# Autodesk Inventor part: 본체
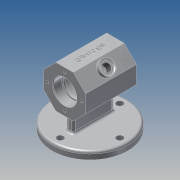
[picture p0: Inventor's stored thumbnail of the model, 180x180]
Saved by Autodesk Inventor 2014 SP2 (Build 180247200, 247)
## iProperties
Created: 2021-02
Part Number: 본체
Material: 알루미늄 6061
Document SubType Name: Modeling
Designer: kb542-10
Density: 2.71 g/cm^3
Appearance: 알루미늄 - 평지
Mass: 558.864 g
Surface Area: 511.644 cm^2
Volume: 206.223 cm^3
Author: kb542-10
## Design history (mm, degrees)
sketch "스케치1"
  geometry: L1 (11.995, -29.007)-(-12.03, -28.993); L2 (-12.03, -28.993)-(-29.007, -11.995); L3 (-29.007, -11.995)-(-28.993, 12.03); L4 (-28.993, 12.03)-(-11.995, 29.007); L5 (-11.995, 29.007)-(12.03, 28.993); L6 (12.03, 28.993)-(29.007, 11.995); L7 (29.007, 11.995)-(28.993, -12.03); L8 (28.993, -12.03)-(11.995, -29.007); 2 further points
  constraints: 16 end point, 1 coincident, 17 other
  dimensions: "d0" = 58 distance between parallel lines of L8 L4
extrude "돌출1" new body sketch "스케치1" stored distance "d1" = 70; taper "d2" = 0 deg
sketch "스케치2"
  geometry: L1 (12.03, 35)-(-11.995, 35) reference; L2 (-11.995, -35)-(12.03, -35) reference; L3 (29.007, 35)-(29.007, -35) reference; L4 (-28.993, 35)-(-28.993, -35) reference; L5 (0.018, 35)-(0.018, -35); L6 (16.018, 35)-(16.018, 23); L7 (16.018, 23)-(14.018, 23); L8 (14.018, 23)-(14.018, 20); L9 (14.018, 20)-(22.018, 20); L10 (22.018, 20)-(22.018, -20); L11 (22.018, -20)-(14.018, -20); L12 (14.018, -20)-(14.018, -23); L13 (14.018, -23)-(16.018, -23); L14 (16.018, -23)-(16.018, -35); L15 (16.018, 35)-(0.018, 35); L16 (16.018, -35)-(0.018, -35); 1 further point
  constraints: 24 end point, 7 parallel, 3 collinear, 3 perpendicular, 2 midpoint, 2 point on line
  dimensions: "d3" = 44 diameter of L10 L5; "d4" = 32 diameter of L6 L5; "d5" = 28 diameter of L8 L5; "d6" = 12 distance of L6.start L6.end; "d7" = 12 distance of L13.end L14.end; "d8" = 3 distance of L7.end L8.end; "d9" = 3 distance of L11.end L12.end
revolve "회전1" sketch "스케치2" stored, may be unused: angle "d10" = 90 deg
node "작업 평면1"
sketch "스케치3"
  geometry: C1 r 52 at (0, 0); 1 further point
  constraints: 1 centre point, 1 coincident
  dimensions: "d12" = 104 diameter of C1
extrude "돌출2" join sketch "스케치3" distance "d13" = 10; taper "d14" = 0 deg
sketch "스케치4"
  geometry: L1 (0, 52)-(0, -52); L2 (52, 0)-(-52, 0); L3 (5, 28)-(-5, 28); L4 (-5, 28)-(-5, -28); L5 (-5, -28)-(5, -28); L6 (5, -28)-(5, 28); A1 r 52 centre (0, 0) between (0, 52) and (0, -52) reference; 4 further points
  constraints: 12 end point, 6 midpoint, 4 point on circle, 2 parallel, 2 perpendicular, 1 horizontal, 1 horizontal alignment, 1 vertical, 1 vertical alignment
  dimensions: "d15" = 10 distance between parallel lines of L4 L6; "d16" = 56 distance between parallel lines of L5 L3
extrude "돌출3" join sketch "스케치4" stored distance "d17" = 10; taper "d18" = 0 deg
sketch "스케치11"
  geometry: L1 (0, 16.988)-(70, 16.988) reference; C1 r 10 at (35, -12.012); 1 further point
  constraints: 1 centre point, 1 coincident
  dimensions: "d47" = 20 diameter of C1
extrude "돌출6" join sketch "스케치11" distance "d48" = 5; taper "d49" = 0 deg
sketch "스케치12"
  geometry: C1 r 10 at (0, 0) reference; C2 r 8 at (0, 0)
  constraints: 1 centre point, 1 coincident
  dimensions: "d50" = 16 diameter of C2
extrude "돌출7" cut sketch "스케치12" distance "d51" = 2; taper "d52" = 0 deg
sketch "스케치13"
  geometry: C1 r 8 at (0, 0) reference; 1 further point
  constraints: 1 coincident
hole "구멍3" sketch "스케치13" at (0, 0) diameter "d53" = 10.917; stored, may be unused: countersink angle "d57" = 90 deg, drill point angle "d59" = 118 deg; dims "d54" = 15, "d55" = 4, "d56" = 2, "d58" = 8
sketch "스케치8"
  geometry: L1 (5, 28)-(5, -28) reference; L2 (5, -28)-(-5, -28) reference; L3 (-52, 0)-(52, 0); L4 (0, 52)-(0, -52); A1 r 52 centre (0, 0) between (-52, 0) and (52, 0) reference; A2 r 41 centre (0, 0) between (0, 41) and (-41, 0); 4 further points
  constraints: 8 point on circle, 4 end point, 4 midpoint, 4 point on line, 2 parallel, 1 centre point, 1 coincident
  dimensions: "d27" = 82 diameter of A2
hole "구멍1" sketch "스케치8" at (0, 41), (-41, 0), (0, -41), (41, 0) diameter "d28" = 9; stored, may be unused: countersink angle "d32" = 90 deg, drill point angle "d34" = 118 deg; dims "d29" = 6, "d30" = 4, "d31" = 2, "d33" = 8
sketch "스케치14" dims "d65" = 46
  geometry: C1 r 16 at (0, 0.018) reference; 6 further points
  constraints: 1 coincident, 1 horizontal alignment, 8 other
  dimensions: "d68" = 360 deg dimension on C1.centre point (23, 0.018) (derived)
hole "구멍4" sketch "스케치14" at (23, 0.018), (0, 23.018), (-23, 0.018), (0, -22.982) diameter "d70" = 3.242; stored, may be unused: countersink angle "d74" = 90 deg, drill point angle "d76" = 118 deg; dims "d71" = 8, "d72" = 4, "d73" = 2, "d75" = 10
sketch "스케치10"
  geometry: L1 (24.024, 0)-(0, 0) reference; L2 (-16.988, 0)-(-16.988, 70) reference; 2 further points
  constraints: 1 other
  dimensions: "d42" = 35 distance from line of L1 point (12.012, 35); "d43" = 29 distance from line of point (12.012, 35) L2
feature "엠보싱1" sketch "스케치10" dims "d44" = 1, "d45" = 0
chamfer "모따기1" distance "d60" = 1; stored, may be unused: second distance "d61" = 2, angle "d62" = 45 deg
fillet "모깎기1" dims "d63" = 3
fillet "모깎기2" dims "d64" = 3
node "솔리드1"
mirror "대칭1"
other parameters: "d11" = -62
